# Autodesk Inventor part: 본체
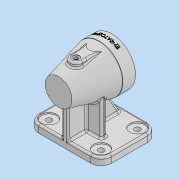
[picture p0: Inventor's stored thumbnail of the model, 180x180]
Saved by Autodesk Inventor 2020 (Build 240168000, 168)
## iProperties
Created: 2024-12
Part Number: 본체
Material: 일반
Document SubType Name: Modeling
Designer: shin
Density: 1 g/cm^3
Appearance: 기본값
Author: shin
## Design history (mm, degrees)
sketch "스케치1"
  geometry: L1 (0, 42)-(0, -42); L2 (0, -42)-(37, -42); L3 (23.5, -42)-(23.5, -24); L4 (23.5, -24)-(32.346, -24); L5 (0, -42)-(23.5, -42); L6 (32.346, -24)-(21.096, 21); L7 (15.5, 31)-(15.5, 34); L8 (15.5, 34)-(0, 34); L9 (21.096, 21)-(17.5, 21); L10 (17.5, 21)-(17.5, 31); L11 (17.5, 31)-(15.5, 31); L12 (23.5, -42)-(37, -42); L13 (21, 42)-(37, -22); L14 (0, 34)-(0, 42); L15 (0, 42)-(37, 42); L16 (37, -42)-(37, 42); L17 (21, 42)-(0, 42); L18 (37, -22)-(37, -42); 1 further point
  constraints: 36 end point, 5 perpendicular, 3 point on line, 3 vertical, 2 collinear, 2 horizontal, 1 midpoint, 1 parallel
  dimensions: "d0" = 84 distance of L2.end L15.end; "d3" = 18 distance of L3.start L3.end; "d4" = 45 distance from line of L4 L6.end; "d5" = 10 distance between parallel lines of L11 L9; "d6" = 3 distance between parallel lines of L8 L11; "d7" = 31 diameter of L7 L1; "d8" = 35 diameter of L10 L1; "d9" = 5 distance between parallel lines of L6 L13; "d10" = 47 diameter of L3 L1; "d11" = 42 diameter of L13.start L1; "d12" = 20 distance of L2.end L13.end; "d17" = 42 distance from line of L15 point (0, 0); "d18" = 74 diameter of L16 L1
revolve "회전1" sketch "스케치1" stored, may be unused: angle "d19" = 90 deg
node "작업 평면1"
sketch "스케치2"
  geometry: L1 (-57, 32)-(57, 32); L2 (57, 32)-(57, -57); L3 (57, -57)-(-57, -57); L4 (-57, -57)-(-57, 32); L5 (-21, 42)-(21, 42) reference; 1 further point
  constraints: 8 end point, 2 parallel, 1 horizontal, 1 perpendicular
  dimensions: "d21" = 89 distance of L3.end L1.start; "d22" = 114 distance of L2.end L3.end; "d23" = 99 distance between parallel lines of L5 L3; "d24" = 57 distance from line of L4 point (0, 0)
extrude "돌출1" join sketch "스케치2" distance "d25" = 12; taper "d26" = 0 deg
sketch "스케치3"
  geometry: L1 (-28, 5)-(28, 5); L2 (28, 5)-(28, -3); L3 (28, -3)-(-28, -3); L4 (-28, -3)-(-28, 5); L5 (-57, -32)-(57, -32) reference; 1 further point
  constraints: 8 end point, 2 parallel, 1 horizontal, 1 perpendicular
  dimensions: "d27" = 56 distance of L1.start L1.end; "d28" = 29 distance between parallel lines of L5 L3; "d29" = 8 distance of L3.end L1.start; "d30" = 28 distance from line of L4 point (0, 0)
extrude "돌출2" join sketch "스케치3" stored distance "d31" = 12; taper "d32" = 0 deg
sketch "스케치4"
  geometry: L1 (-70, -50)-(-37, -30.947); L2 (-37, -22)-(-37, -42) reference; L3 (-70, 32)-(-23.5, 32); L4 (-21, 42)-(-37, -22) reference; 2 further points
  constraints: 4 end point, 2 point on line, 1 horizontal
  dimensions: "d34" = 7 distance of L1.start point (-70, -57)
feature "리브1" dims "d35" = 1, "d36" = 10, "d37" = 0, "d38" = 0, "d39" = 1, "d40" = 1
feature "리브2" dims "d41" = 1, "d42" = 10, "d43" = 0, "d44" = 0, "d45" = 1, "d46" = 1
sketch "스케치6"
  geometry: L1 (57, 57)-(-57, 57) reference; 2 further points
  dimensions: "d47" = 41 horizontal distance of point (0, 0) point (-41, 41); "d49" = 16 distance from line of point (-41, 41) L1
hole "구멍1" sketch "스케치6" at (-41, 41) diameter "d50" = 9; stored, may be unused: countersink angle "d54" = 90 deg, drill point angle "d56" = 118 deg; dims "d51" = 6, "d52" = 4, "d53" = 2, "d55" = 8
sketch "스케치7"
  geometry: C1 r 4.5 at (-41, 41) reference; C2 r 12 at (-41, 41); 1 further point
  constraints: 1 centre point, 1 coincident
  dimensions: "d59" = 24 diameter of C2
fillet "모깎기1" dims "d57" = 16
fillet "모깎기2" dims "d58" = 3
extrude "돌출3" cut sketch "스케치7" distance "d60" = 2; taper "d61" = 0 deg
node "작업 평면2"
sketch "스케치8"
  geometry: L1 (-37, -42)-(37, -42) reference; L2 (-37, -22)-(37, -22) reference; L3 (10, 14)-(10, -22); L4 (-10, 14)-(-10, -22); A1 r 10 centre (0, 14) between (10, 14) and (-10, 14); 3 further points
  constraints: 4 end point, 2 point on circle, 2 point on line, 2 tangent, 1 centre point, 1 perpendicular, 1 vertical, 1 vertical alignment
  dimensions: "d65" = 20 diameter of A1; "d66" = 56 distance from line of L1 A1.centre
extrude "돌출4" join sketch "스케치8" stored distance "d67" = 2; taper "d68" = 0 deg
sketch "스케치9"
  geometry: C1 r 5 at (0, -14); A1 r 10 centre (0, -14) between (-10, -14) and (10, -14) reference; 1 further point
  constraints: 1 centre point, 1 coincident
  dimensions: "d69" = 10 diameter of C1
extrude "돌출5" cut sketch "스케치9" distance "d70" = 1; taper "d71" = 0 deg
sketch "스케치10"
  geometry: C1 r 5 at (0, 0) reference; C2 r 3 at (0, 0); 1 further point
  constraints: 1 centre point, 1 coincident
  dimensions: "d72" = 6 diameter of C2
extrude "돌출6" cut sketch "스케치10" stored distance "d73" = 1; taper "d74" = 0 deg
feature "스레드1" dims "d75" = 4.75, "d76" = 0
node "작업 평면3"
sketch "스케치11"
  geometry: L1 (-37, -10)-(37, -10) reference; 2 further points
  constraints: 1 vertical alignment, 1 other
  dimensions: "d83" = 9 distance from line of L1 point (0, -1)
feature "엠보싱1" sketch "스케치11" dims "d20" = -82, "d84" = 0.5, "d85" = 0
fillet "모깎기3" dims "d86" = 3
fillet "모깎기4" dims "d87" = 3
fillet "모깎기5" dims "d88" = 3
fillet "모깎기6" dims "d89" = 3
fillet "모깎기7" dims "d90" = 3
fillet "모깎기8" dims "d91" = 3
fillet "모깎기9" dims "d92" = 0.3
fillet "모깎기10" dims "d93" = 3
chamfer "모따기1" distance "d94" = 1; stored, may be unused: second distance "d95" = 2, angle "d96" = 45 deg
chamfer "모따기2" distance "d97" = 1; stored, may be unused: second distance "d98" = 2, angle "d99" = 45 deg
fillet "모깎기11" dims "d100" = 5
sketch "스케치12" dims "d101" = 57
  geometry: 3 further points
  constraints: 2 vertical alignment, 1 coincident, 2 other
hole "구멍2" sketch "스케치12" at (0, 28.5) diameter "d102" = 3.242; stored, may be unused: countersink angle "d106" = 90 deg, drill point angle "d108" = 118 deg; dims "d103" = 8, "d104" = 4, "d105" = 2, "d107" = 10
node "솔리드1"
pattern_linear "직사각형 패턴1" dims "d79" = 82, "d82" = 57
pattern_circular "원형 패턴1" dims angle "d110" = 360 deg
feature "A9D066F2-1C7D-4E18-AEED-F7BC21143FA4" dims "d102" = 3.242, "d103" = 8, "d104" = 4, "d105" = 2, "d106" = 90 deg, "d107" = 10, "d108" = 118 deg
other parameters: "d62" = -115
